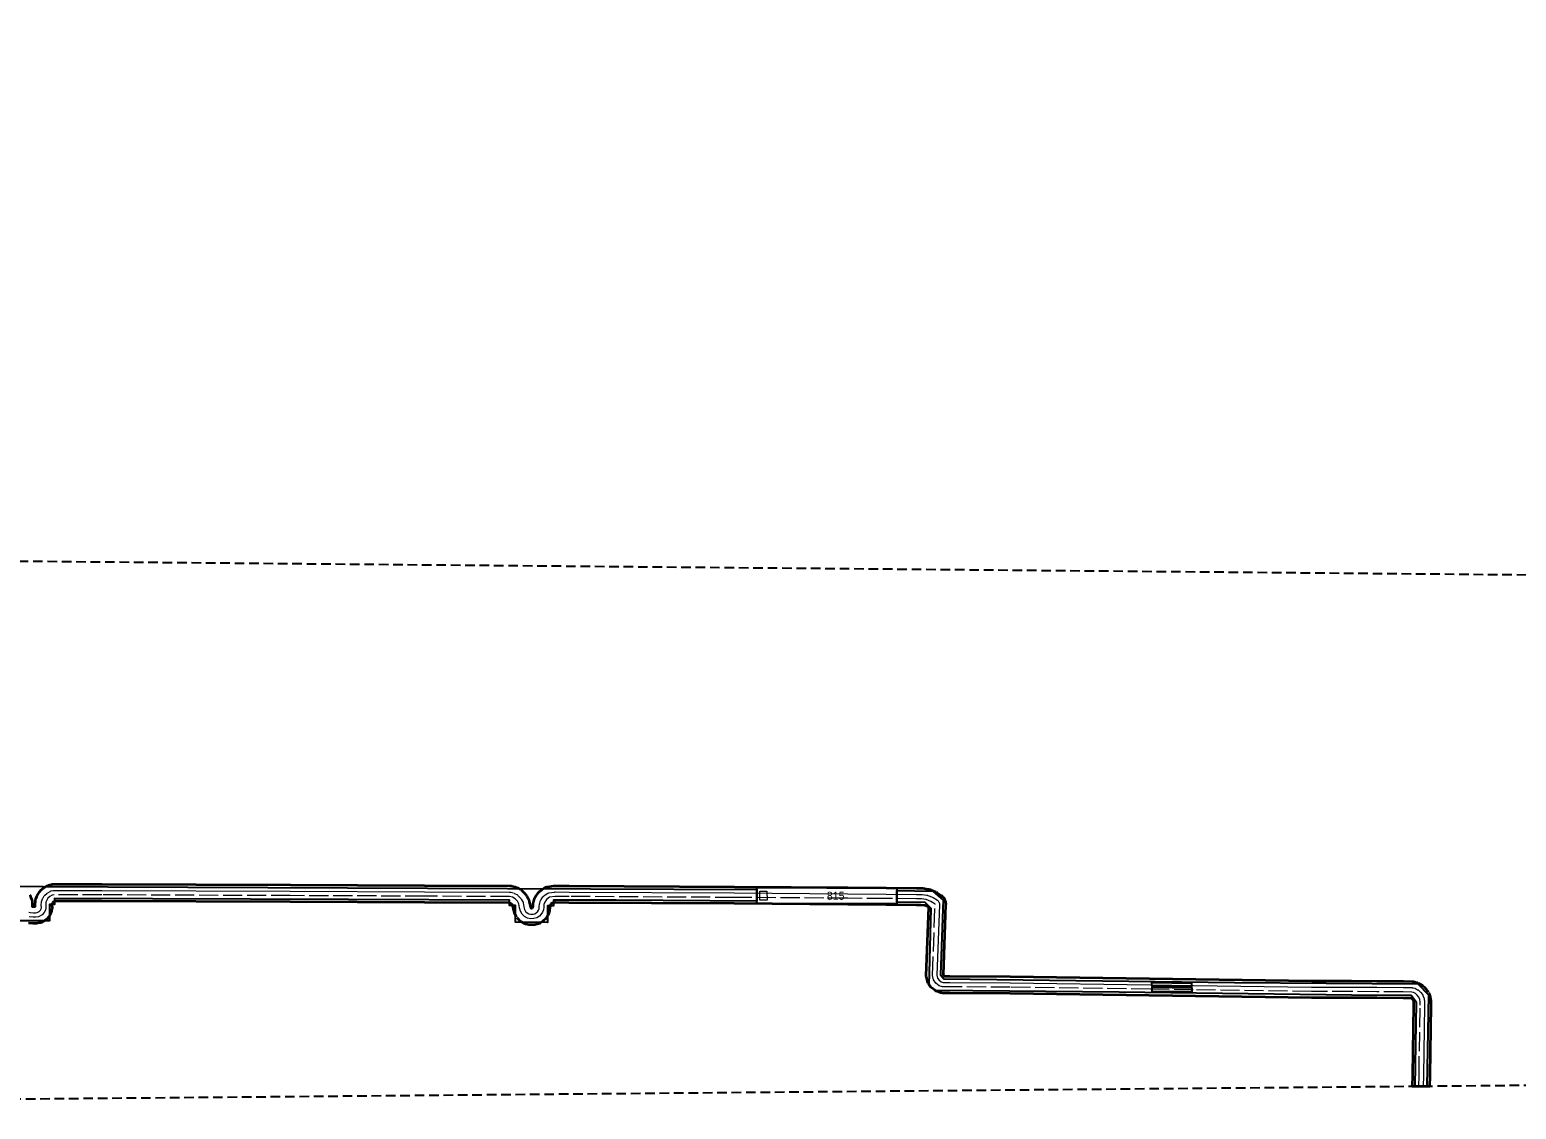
# Model space of a CAD drawing. Extents: x -451331 to -449998, y -1101254 to -1101132.
# Drawn here: x -450332.1 to -450164.9, y -1101253.5 to -1101132.1 of the extents above; entities that cross this region are included whole.
import ezdxf

# ---------------------------------------------------------------- set-up
doc = ezdxf.new("R2010")
doc.units = 0
doc.header["$LTSCALE"] = 0.36
doc.linetypes.add('LONG_DASHED', pattern=[7.5, 6, -1.5])
doc.linetypes.add('MEDIUM_DASHED', pattern=[4.5, 3, -1.5])
for name, color, linetype, lineweight in [('2', 7, 'Continuous', 13), ('3', 7, 'Continuous', 25), ('62', 7, 'MEDIUM_DASHED', 25), ('8', 7, 'Continuous', 35)]:
    doc.layers.add(name, color=color, linetype=linetype, lineweight=lineweight)

msp = doc.modelspace()

# ---------------------------------------------------------------- linework, layer by layer
at = {"layer": '2'}
msp.add_line((-450206.063, -1101239.511), (-450201.195, -1101239.579), dxfattribs=at)
at = {"layer": '2', "linetype": 'LONG_DASHED'}
msp.add_line((-450201.234, -1101240.079), (-450206.048, -1101240.011), dxfattribs=at)
at = {"layer": '2'}
for points in [[(-450332.19, -1101231.332), (-450332.047, -1101231.394), (-450331.672, -1101231.415), (-450331.453, -1101231.422), (-450331.251, -1101231.39), (-450331.011, -1101231.262), (-450330.875, -1101231.11), (-450330.804, -1101230.96), (-450330.775, -1101230.812), (-450330.785, -1101230.542), (-450330.754, -1101230.194), (-450330.744, -1101230.131), (-450330.726, -1101230.069), (-450330.64, -1101229.83), (-450330.617, -1101229.778), (-450330.589, -1101229.729), (-450330.452, -1101229.517), (-450330.417, -1101229.469), (-450330.376, -1101229.425), (-450330.172, -1101229.233), (-450330.121, -1101229.19), (-450330.064, -1101229.155), (-450329.788, -1101229.008), (-450329.733, -1101228.983), (-450329.674, -1101228.964), (-450329.455, -1101228.909), (-450329.394, -1101228.897), (-450329.332, -1101228.894), (-450323.973, -1101228.903), (-450302.779, -1101228.988), (-450287.698, -1101229.048), (-450278.118, -1101229.086), (-450278.056, -1101229.09), (-450277.995, -1101229.102), (-450277.687, -1101229.182)], [(-450277.623, -1101229.203), (-450277.563, -1101229.232), (-450277.248, -1101229.413), (-450277.19, -1101229.452), (-450277.138, -1101229.498), (-450276.883, -1101229.761), (-450276.84, -1101229.813), (-450276.803, -1101229.87), (-450276.64, -1101230.168), (-450276.609, -1101230.236), (-450276.589, -1101230.308), (-450276.501, -1101230.737), (-450276.431, -1101231.048), (-450276.314, -1101231.255), (-450276.153, -1101231.415), (-450275.94, -1101231.535), (-450275.736, -1101231.585), (-450275.468, -1101231.576), (-450275.275, -1101231.516), (-450275.085, -1101231.399), (-450274.989, -1101231.305), (-450274.858, -1101231.106), (-450274.807, -1101230.966), (-450274.779, -1101230.735), (-450274.762, -1101230.463), (-450274.754, -1101230.398), (-450274.737, -1101230.334), (-450274.64, -1101230.045), (-450274.613, -1101229.979), (-450274.576, -1101229.918), (-450274.379, -1101229.636), (-450274.323, -1101229.57), (-450274.257, -1101229.515), (-450273.902, -1101229.264), (-450273.837, -1101229.225), (-450273.767, -1101229.196), (-450273.693, -1101229.179), (-450273.088, -1101229.081), (-450273.005, -1101229.074), (-450271.433, -1101229.085), (-450252.85, -1101229.189), (-450240.078, -1101229.28), (-450235.767, -1101229.314), (-450232.361, -1101229.341), (-450231.812, -1101229.346), (-450231.742, -1101229.352), (-450231.188, -1101229.436), (-450231.136, -1101229.447), (-450231.085, -1101229.463), (-450230.568, -1101229.659), (-450230.518, -1101229.681), (-450230.472, -1101229.708), (-450230.005, -1101230.013), (-450229.937, -1101230.066), (-450229.88, -1101230.13), (-450229.834, -1101230.203), (-450229.801, -1101230.282), (-450229.783, -1101230.366), (-450229.779, -1101230.452), (-450229.781, -1101230.511), (-450230.058, -1101238.432), (-450229.989, -1101238.752), (-450229.828, -1101238.989), (-450229.588, -1101239.165), (-450229.358, -1101239.241), (-450228.612, -1101239.248), (-450221.825, -1101239.288), (-450206.063, -1101239.511)], [(-450201.195, -1101239.579), (-450187.923, -1101239.767), (-450183.448, -1101239.783), (-450180.607, -1101239.793), (-450177.632, -1101239.803), (-450176.636, -1101239.831), (-450176.57, -1101239.837), (-450176.505, -1101239.852), (-450176.325, -1101239.907), (-450176.28, -1101239.923), (-450176.237, -1101239.943), (-450176.005, -1101240.065), (-450175.958, -1101240.093), (-450175.915, -1101240.127), (-450175.72, -1101240.292), (-450175.679, -1101240.331), (-450175.642, -1101240.375), (-450175.472, -1101240.605), (-450175.438, -1101240.657), (-450175.411, -1101240.713), (-450175.296, -1101240.993), (-450175.276, -1101241.052), (-450175.264, -1101241.114), (-450175.224, -1101241.402), (-450175.22, -1101241.478), (-450175.225, -1101241.808), (-450175.349, -1101249.7), (-450175.368, -1101250.947)]]:
    msp.add_lwpolyline(points, dxfattribs=at)
at = {"layer": '2', "linetype": 'LONG_DASHED'}
for points in [[(-450206.048, -1101240.011), (-450221.83, -1101239.788), (-450228.616, -1101239.748), (-450229.44, -1101239.74), (-450229.82, -1101239.616), (-450230.194, -1101239.341), (-450230.457, -1101238.952), (-450230.56, -1101238.477), (-450230.281, -1101230.493), (-450230.279, -1101230.432), (-450230.745, -1101230.127), (-450231.262, -1101229.931), (-450231.817, -1101229.846), (-450232.366, -1101229.841), (-450235.771, -1101229.814), (-450240.081, -1101229.78), (-450252.853, -1101229.689), (-450271.436, -1101229.585), (-450273.008, -1101229.574), (-450273.614, -1101229.672), (-450273.969, -1101229.923), (-450274.166, -1101230.204), (-450274.263, -1101230.493), (-450274.281, -1101230.78), (-450274.317, -1101231.083), (-450274.409, -1101231.333), (-450274.601, -1101231.626), (-450274.776, -1101231.795), (-450275.066, -1101231.974), (-450275.384, -1101232.074), (-450275.788, -1101232.087), (-450276.125, -1101232.004), (-450276.457, -1101231.818), (-450276.716, -1101231.56), (-450276.902, -1101231.229), (-450276.99, -1101230.843), (-450277.079, -1101230.408), (-450277.242, -1101230.11), (-450277.497, -1101229.847), (-450277.812, -1101229.666), (-450278.12, -1101229.586), (-450287.7, -1101229.548), (-450302.781, -1101229.488), (-450323.975, -1101229.403), (-450329.333, -1101229.394), (-450329.553, -1101229.449), (-450329.829, -1101229.596), (-450330.033, -1101229.789), (-450330.17, -1101230), (-450330.256, -1101230.239), (-450330.284, -1101230.555), (-450330.273, -1101230.852), (-450330.326, -1101231.117), (-450330.454, -1101231.389), (-450330.697, -1101231.662), (-450331.09, -1101231.872), (-450331.421, -1101231.923), (-450331.693, -1101231.915), (-450332.164, -1101231.888)], [(-450175.869, -1101250.951), (-450175.849, -1101249.692), (-450175.725, -1101241.8), (-450175.72, -1101241.47), (-450175.759, -1101241.182), (-450175.874, -1101240.903), (-450176.044, -1101240.673), (-450176.239, -1101240.508), (-450176.47, -1101240.385), (-450176.65, -1101240.331), (-450177.64, -1101240.303), (-450180.609, -1101240.293), (-450183.45, -1101240.283), (-450187.927, -1101240.267), (-450201.234, -1101240.079)]]:
    msp.add_lwpolyline(points, dxfattribs=at)
at = {"layer": '3'}
msp.add_lwpolyline([(-450345.044, -1101228.383), (-450323.284, -1101228.506), (-450278.369, -1101228.685), (-450250.301, -1101228.807), (-450250.31, -1101230.105), (-450266.151, -1101230.014), (-450273.179, -1101230.007), (-450273.169, -1101230.627), (-450273.87, -1101230.62), (-450273.864, -1101232.505), (-450277.449, -1101232.466), (-450277.451, -1101230.586), (-450278.13, -1101230.58), (-450278.127, -1101229.997), (-450296.254, -1101229.914), (-450329.293, -1101229.796), (-450329.282, -1101230.495), (-450329.876, -1101230.48), (-450329.864, -1101232.315), (-450333.399, -1101232.315)], dxfattribs=at)
for points in [[(-450250.312, -1101230.378), (-450250.299, -1101228.579), (-450234.556, -1101228.641), (-450234.563, -1101230.412)], [(-450234.557, -1101228.923), (-450230.515, -1101228.991), (-450229.379, -1101229.996), (-450229.434, -1101232.014), (-450229.657, -1101238.397), (-450229.292, -1101238.841), (-450196.59, -1101239.245), (-450175.994, -1101239.423), (-450174.79, -1101240.627), (-450174.967, -1101250.943), (-450176.269, -1101250.955), (-450176.12, -1101241.494), (-450176.715, -1101240.729), (-450183.451, -1101240.683), (-450209.577, -1101240.361), (-450230.135, -1101240.161), (-450230.932, -1101239.591), (-450230.697, -1101230.936), (-450231.373, -1101230.269), (-450234.563, -1101230.216)], [(-450205.891, -1101239.239), (-450201.419, -1101239.324), (-450201.419, -1101239.773), (-450205.877, -1101239.72)], [(-450205.876, -1101239.778), (-450201.404, -1101239.863), (-450201.404, -1101240.312), (-450205.862, -1101240.259)]]:
    msp.add_lwpolyline(points, close=True, dxfattribs=at)
at = {"layer": '3', "lineweight": 13}
msp.add_lwpolyline([(-450249.99, -1101228.98), (-450249.183, -1101228.967), (-450249.166, -1101229.985), (-450249.973, -1101229.998)], close=True, dxfattribs=at)
at = {"layer": '62'}
msp.add_lwpolyline([(-450786.261, -1101210.25), (-451322.174, -1101190.711), (-451330.547, -1101132.096), (-450766.722, -1101150.239), (-450459.689, -1101190.711), (-449997.743, -1101194.898), (-449997.743, -1101249.327), (-450456.897, -1101253.514)], close=True, dxfattribs=at)
at = {"layer": '8'}
for points in [[(-450332.077, -1101229.403), (-450332.052, -1101229.45), (-450332.031, -1101229.492), (-450332.02, -1101229.517), (-450332, -1101229.567), (-450331.987, -1101229.602), (-450331.865, -1101229.953), (-450331.862, -1101229.962), (-450331.854, -1101229.988), (-450331.839, -1101230.039), (-450331.828, -1101230.085), (-450331.822, -1101230.111), (-450331.813, -1101230.164), (-450331.807, -1101230.211), (-450331.804, -1101230.238), (-450331.801, -1101230.291), (-450331.799, -1101230.328), (-450331.794, -1101230.684), (-450331.793, -1101230.707), (-450331.642, -1101230.716), (-450331.497, -1101230.72), (-450331.479, -1101230.717), (-450331.485, -1101230.567), (-450331.484, -1101230.504), (-450331.482, -1101230.479), (-450331.451, -1101230.131), (-450331.448, -1101230.102), (-450331.442, -1101230.059), (-450331.439, -1101230.04), (-450331.431, -1101230), (-450331.422, -1101229.958), (-450331.414, -1101229.925), (-450331.407, -1101229.9), (-450331.394, -1101229.859), (-450331.384, -1101229.831), (-450331.298, -1101229.592), (-450331.292, -1101229.575), (-450331.283, -1101229.555), (-450331.261, -1101229.503), (-450331.239, -1101229.455), (-450331.226, -1101229.432), (-450331.198, -1101229.382), (-450331.177, -1101229.348), (-450331.04, -1101229.137), (-450331.036, -1101229.13), (-450331.016, -1101229.102), (-450330.981, -1101229.054), (-450330.956, -1101229.022), (-450330.927, -1101228.99), (-450330.886, -1101228.946), (-450330.864, -1101228.924), (-450330.857, -1101228.916), (-450330.653, -1101228.724), (-450330.63, -1101228.703), (-450330.596, -1101228.674), (-450330.571, -1101228.653), (-450330.547, -1101228.636), (-450330.511, -1101228.61), (-450330.474, -1101228.585), (-450330.459, -1101228.576), (-450330.421, -1101228.553), (-450330.394, -1101228.538), (-450330.117, -1101228.39), (-450330.094, -1101228.378), (-450330.079, -1101228.371), (-450330.024, -1101228.346), (-450329.97, -1101228.324), (-450329.944, -1101228.315), (-450329.886, -1101228.297), (-450329.845, -1101228.285), (-450329.623, -1101228.23), (-450329.583, -1101228.221), (-450329.522, -1101228.209), (-450329.487, -1101228.204), (-450329.436, -1101228.199), (-450329.374, -1101228.195), (-450329.35, -1101228.194), (-450329.331, -1101228.194), (-450323.971, -1101228.203), (-450302.776, -1101228.288), (-450287.695, -1101228.348), (-450278.115, -1101228.386), (-450278.071, -1101228.387), (-450278.009, -1101228.392), (-450278, -1101228.392), (-450277.924, -1101228.402), (-450277.862, -1101228.415), (-450277.819, -1101228.424), (-450277.511, -1101228.504), (-450277.483, -1101228.512), (-450277.438, -1101228.526), (-450277.379, -1101228.547), (-450277.338, -1101228.564), (-450277.33, -1101228.567), (-450277.281, -1101228.59), (-450277.241, -1101228.61), (-450277.223, -1101228.62), (-450277.214, -1101228.625), (-450276.899, -1101228.807), (-450276.871, -1101228.823)], [(-450276.832, -1101228.848), (-450276.806, -1101228.865), (-450276.779, -1101228.886), (-450276.743, -1101228.914), (-450276.711, -1101228.94), (-450276.693, -1101228.956), (-450276.659, -1101228.988), (-450276.636, -1101229.011), (-450276.381, -1101229.274), (-450276.369, -1101229.287), (-450276.359, -1101229.297), (-450276.329, -1101229.331), (-450276.291, -1101229.379), (-450276.263, -1101229.416), (-450276.228, -1101229.468), (-450276.205, -1101229.507), (-450276.2, -1101229.514), (-450276.189, -1101229.534), (-450276.026, -1101229.832), (-450276.01, -1101229.863), (-450275.989, -1101229.907), (-450275.981, -1101229.923), (-450275.961, -1101229.972), (-450275.944, -1101230.019), (-450275.937, -1101230.04), (-450275.923, -1101230.085), (-450275.911, -1101230.133), (-450275.905, -1101230.16), (-450275.903, -1101230.168), (-450275.817, -1101230.59), (-450275.771, -1101230.793), (-450275.751, -1101230.828), (-450275.728, -1101230.851), (-450275.681, -1101230.877), (-450275.662, -1101230.882), (-450275.586, -1101230.88), (-450275.568, -1101230.874), (-450275.526, -1101230.848), (-450275.491, -1101230.795), (-450275.477, -1101230.672), (-450275.461, -1101230.419), (-450275.458, -1101230.389), (-450275.454, -1101230.346), (-450275.449, -1101230.308), (-450275.445, -1101230.285), (-450275.436, -1101230.242), (-450275.425, -1101230.192), (-450275.422, -1101230.183), (-450275.41, -1101230.141), (-450275.401, -1101230.111), (-450275.304, -1101229.822), (-450275.292, -1101229.791), (-450275.275, -1101229.746), (-450275.248, -1101229.685), (-450275.226, -1101229.643), (-450275.222, -1101229.635), (-450275.193, -1101229.584), (-450275.168, -1101229.544), (-450275.159, -1101229.531), (-450275.149, -1101229.516), (-450274.952, -1101229.235), (-450274.928, -1101229.202), (-450274.892, -1101229.157), (-450274.882, -1101229.144), (-450274.839, -1101229.097), (-450274.798, -1101229.056), (-450274.791, -1101229.049), (-450274.738, -1101229.002), (-450274.691, -1101228.965), (-450274.661, -1101228.943), (-450274.305, -1101228.692), (-450274.273, -1101228.67), (-450274.224, -1101228.64), (-450274.16, -1101228.604), (-450274.154, -1101228.602), (-450274.103, -1101228.577), (-450274.04, -1101228.551), (-450274.03, -1101228.547), (-450273.976, -1101228.529), (-450273.915, -1101228.511), (-450273.899, -1101228.507), (-450273.844, -1101228.495), (-450273.805, -1101228.488), (-450273.199, -1101228.39), (-450273.181, -1101228.387), (-450273.17, -1101228.386), (-450273.129, -1101228.381), (-450273.071, -1101228.376), (-450273.029, -1101228.375), (-450273.023, -1101228.375), (-450273, -1101228.374), (-450271.429, -1101228.385), (-450252.845, -1101228.489), (-450240.072, -1101228.58), (-450235.762, -1101228.614), (-450232.355, -1101228.641), (-450231.804, -1101228.647), (-450231.78, -1101228.647), (-450231.745, -1101228.649), (-450231.721, -1101228.65)], [(-450231.696, -1101228.653), (-450231.662, -1101228.657), (-450231.637, -1101228.66), (-450231.083, -1101228.744), (-450231.058, -1101228.748), (-450231.046, -1101228.751), (-450230.994, -1101228.761), (-450230.934, -1101228.777), (-450230.922, -1101228.78), (-450230.872, -1101228.796), (-450230.837, -1101228.809), (-450230.319, -1101229.005), (-450230.295, -1101229.015), (-450230.284, -1101229.019), (-450230.235, -1101229.041), (-450230.179, -1101229.069), (-450230.167, -1101229.076), (-450230.12, -1101229.103), (-450230.088, -1101229.122), (-450229.622, -1101229.427), (-450229.603, -1101229.441), (-450229.589, -1101229.45), (-450229.543, -1101229.484), (-450229.498, -1101229.521), (-450229.481, -1101229.536), (-450229.439, -1101229.575), (-450229.403, -1101229.612), (-450229.384, -1101229.633), (-450229.347, -1101229.677), (-450229.318, -1101229.713), (-450229.298, -1101229.741), (-450229.266, -1101229.788), (-450229.245, -1101229.822), (-450229.226, -1101229.857), (-450229.199, -1101229.908), (-450229.184, -1101229.94), (-450229.167, -1101229.982), (-450229.146, -1101230.035), (-450229.137, -1101230.063), (-450229.123, -1101230.112), (-450229.109, -1101230.168), (-450229.103, -1101230.19), (-450229.093, -1101230.246), (-450229.086, -1101230.303), (-450229.084, -1101230.32), (-450229.08, -1101230.383), (-450229.079, -1101230.44), (-450229.079, -1101230.452), (-450229.08, -1101230.481), (-450229.082, -1101230.537), (-450229.356, -1101238.37), (-450229.334, -1101238.471), (-450229.317, -1101238.496), (-450229.264, -1101238.535), (-450229.242, -1101238.542), (-450228.606, -1101238.548), (-450221.821, -1101238.588), (-450221.815, -1101238.588), (-450187.917, -1101239.067), (-450183.446, -1101239.083), (-450180.604, -1101239.092), (-450177.63, -1101239.103), (-450177.613, -1101239.103), (-450176.616, -1101239.131), (-450176.585, -1101239.133), (-450176.538, -1101239.136), (-450176.479, -1101239.143), (-450176.435, -1101239.15), (-450176.418, -1101239.153), (-450176.374, -1101239.163), (-450176.331, -1101239.174), (-450176.302, -1101239.182), (-450176.121, -1101239.237), (-450176.09, -1101239.248), (-450176.045, -1101239.263), (-450176.008, -1101239.278), (-450175.984, -1101239.289), (-450175.94, -1101239.309), (-450175.911, -1101239.324), (-450175.679, -1101239.446), (-450175.666, -1101239.453), (-450175.645, -1101239.465), (-450175.599, -1101239.493), (-450175.556, -1101239.521), (-450175.535, -1101239.536), (-450175.491, -1101239.569), (-450175.462, -1101239.593), (-450175.267, -1101239.758), (-450175.259, -1101239.765), (-450175.237, -1101239.785), (-450175.196, -1101239.824), (-450175.165, -1101239.856), (-450175.141, -1101239.883), (-450175.105, -1101239.927), (-450175.08, -1101239.958), (-450174.91, -1101240.188), (-450174.885, -1101240.224), (-450174.851, -1101240.276), (-450174.835, -1101240.302), (-450174.808, -1101240.352)], [(-450277.326, -1101231.903), (-450277.512, -1101231.572), (-450277.556, -1101231.481), (-450277.585, -1101231.384), (-450277.673, -1101230.998), (-450277.676, -1101230.983), (-450277.744, -1101230.651), (-450277.81, -1101230.529), (-450277.931, -1101230.405), (-450278.079, -1101230.32), (-450278.211, -1101230.285), (-450287.703, -1101230.248), (-450302.784, -1101230.188), (-450323.977, -1101230.103), (-450329.247, -1101230.094), (-450329.299, -1101230.107), (-450329.417, -1101230.17), (-450329.491, -1101230.24), (-450329.538, -1101230.313), (-450329.567, -1101230.392), (-450329.583, -1101230.574), (-450329.574, -1101230.827), (-450329.576, -1101230.907), (-450329.587, -1101230.987), (-450329.639, -1101231.252), (-450329.661, -1101231.336), (-450329.693, -1101231.416), (-450329.821, -1101231.688), (-450329.87, -1101231.776), (-450329.932, -1101231.856), (-450330.175, -1101232.128), (-450330.233, -1101232.186), (-450330.298, -1101232.236), (-450330.367, -1101232.279), (-450330.76, -1101232.489), (-450330.869, -1101232.536), (-450330.983, -1101232.563), (-450331.315, -1101232.614), (-450331.365, -1101232.62), (-450331.441, -1101232.622), (-450331.713, -1101232.615), (-450331.733, -1101232.614), (-450332.204, -1101232.587)], [(-450174.781, -1101240.407), (-450174.774, -1101240.424), (-450174.763, -1101240.447), (-450174.649, -1101240.727), (-450174.633, -1101240.768), (-450174.612, -1101240.83), (-450174.592, -1101240.905), (-450174.59, -1101240.914), (-450174.578, -1101240.975), (-450174.57, -1101241.019), (-450174.531, -1101241.307), (-450174.528, -1101241.328), (-450174.528, -1101241.334), (-450174.524, -1101241.372), (-450174.521, -1101241.425), (-450174.52, -1101241.463), (-450174.52, -1101241.478), (-450174.52, -1101241.489), (-450174.525, -1101241.819), (-450174.649, -1101249.711), (-450174.668, -1101250.94), (-450176.569, -1101250.957), (-450176.549, -1101249.681), (-450176.425, -1101241.789), (-450176.42, -1101241.512), (-450176.44, -1101241.366), (-450176.488, -1101241.249), (-450176.559, -1101241.154), (-450176.633, -1101241.091), (-450176.738, -1101241.036), (-450176.764, -1101241.028), (-450177.651, -1101241.003), (-450180.611, -1101240.993), (-450183.452, -1101240.983), (-450187.929, -1101240.967), (-450187.937, -1101240.967), (-450221.837, -1101240.488), (-450228.621, -1101240.448), (-450229.447, -1101240.44), (-450229.554, -1101240.431), (-450229.658, -1101240.405), (-450230.038, -1101240.281), (-450230.14, -1101240.238), (-450230.234, -1101240.18), (-450230.608, -1101239.906), (-450230.698, -1101239.827), (-450230.773, -1101239.734), (-450231.037, -1101239.345), (-450231.082, -1101239.268), (-450231.117, -1101239.186), (-450231.141, -1101239.1), (-450231.244, -1101238.626), (-450231.257, -1101238.54), (-450231.26, -1101238.453), (-450230.992, -1101230.802), (-450231.064, -1101230.754), (-450231.441, -1101230.611), (-450231.874, -1101230.546), (-450232.372, -1101230.541), (-450235.776, -1101230.514), (-450240.086, -1101230.48), (-450252.857, -1101230.389), (-450271.44, -1101230.285), (-450272.954, -1101230.275), (-450273.342, -1101230.337), (-450273.466, -1101230.425), (-450273.535, -1101230.523), (-450273.57, -1101230.629), (-450273.582, -1101230.823), (-450273.585, -1101230.854), (-450273.586, -1101230.862), (-450273.622, -1101231.166), (-450273.636, -1101231.246), (-450273.66, -1101231.324), (-450273.752, -1101231.574), (-450273.784, -1101231.648), (-450273.824, -1101231.717), (-450274.016, -1101232.01), (-450274.062, -1101232.072), (-450274.114, -1101232.129), (-450274.289, -1101232.298), (-450274.346, -1101232.348), (-450274.408, -1101232.391), (-450274.698, -1101232.57), (-450274.775, -1101232.611), (-450274.857, -1101232.642), (-450275.175, -1101232.742), (-450275.267, -1101232.764), (-450275.362, -1101232.773), (-450275.766, -1101232.786), (-450275.861, -1101232.783), (-450275.955, -1101232.767), (-450276.292, -1101232.684), (-450276.381, -1101232.655), (-450276.466, -1101232.615), (-450276.799, -1101232.429), (-450276.879, -1101232.377), (-450276.952, -1101232.314), (-450277.211, -1101232.056), (-450277.274, -1101231.983)]]:
    msp.add_lwpolyline(points, dxfattribs=at)

# ---------------------------------------------------------------- texts
at = {"layer": '3'}
msp.add_text('815 ', height=0.9, dxfattribs=at).set_placement((-450242.453, -1101229.952))

doc.saveas('drawing.dxf')
